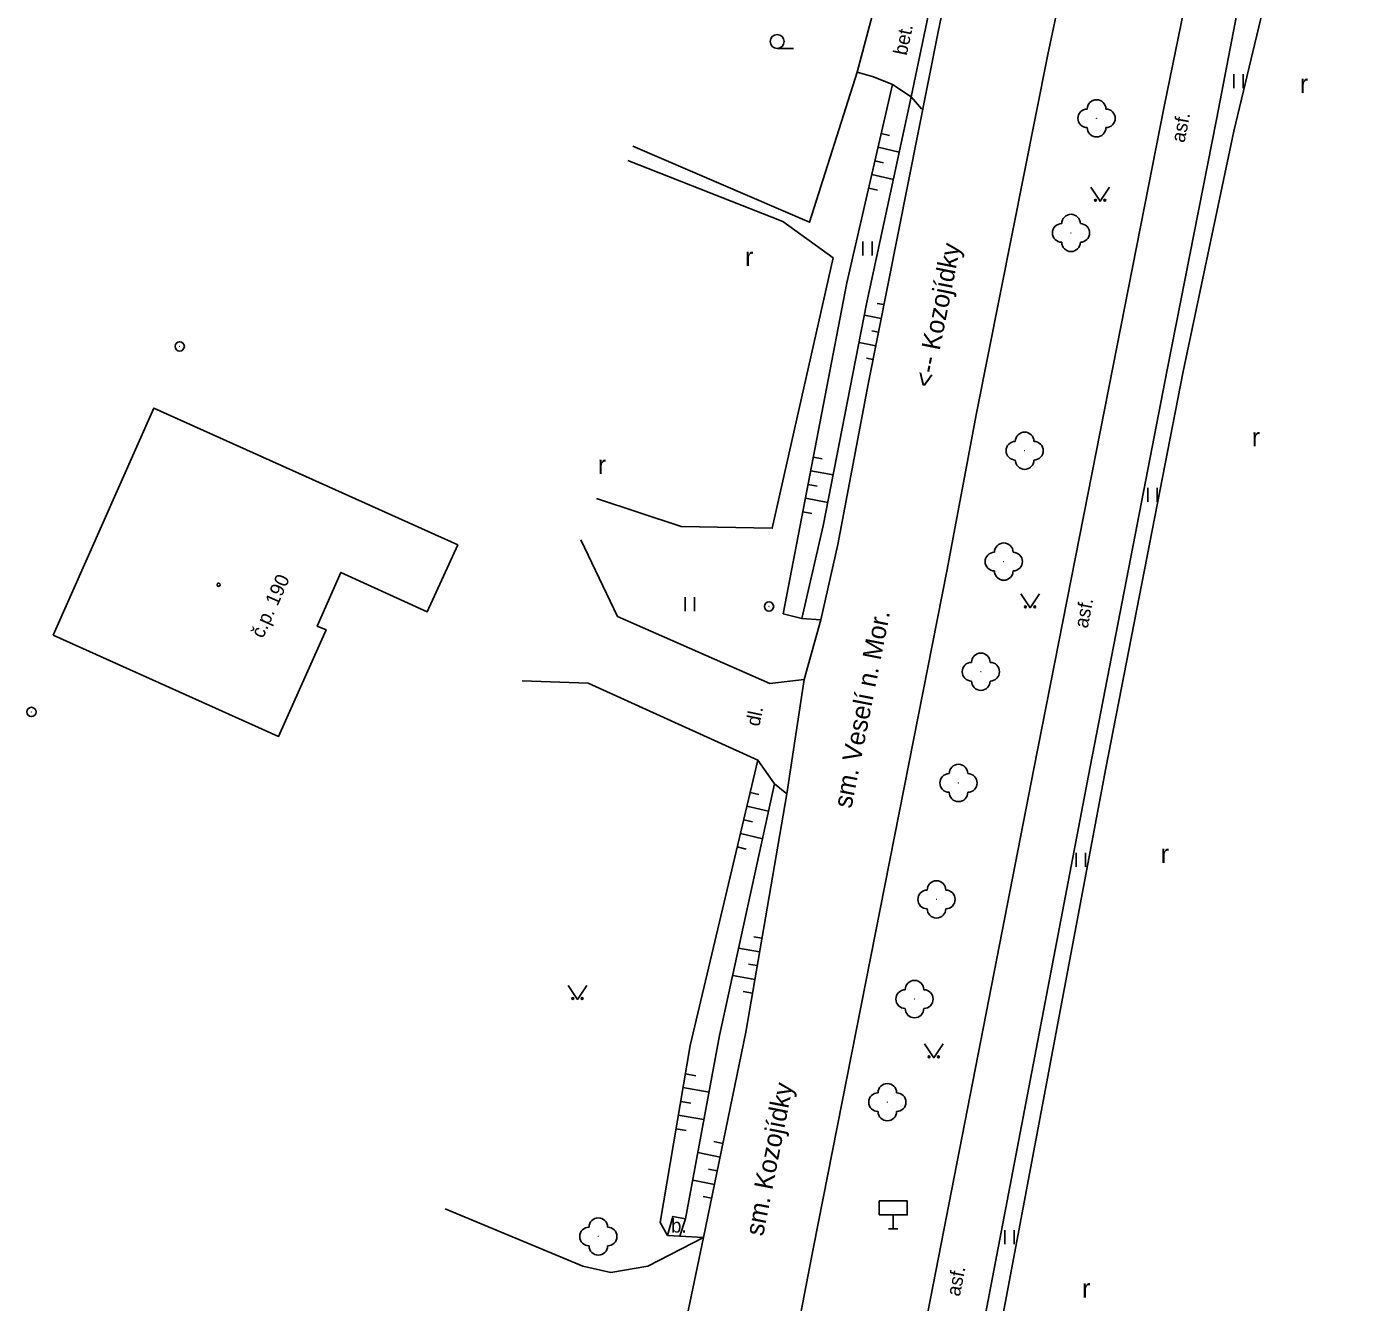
# Model space of a CAD drawing. Extents: x -544674 to -541478, y -1199076 to -1195527.
# Drawn here: x -543843.4 to -543771.7, y -1196778.9 to -1196710.5 of the extents above; entities that cross this region are included whole.
import ezdxf

# ---------------------------------------------------------------- set-up
doc = ezdxf.new("R2010")
doc.units = 0
for name, color, linetype in [('BUDOVY_MĚŘ', 7, 'Continuous'), ('NÁZVY_ULIC_TOK_SMĚR', 7, 'Continuous'), ('POMOC_POPIS', 7, 'Continuous'), ('ROZHRANÍ_PLOCH', 7, 'Continuous'), ('VÝŠKOPIS', 7, 'Continuous'), ('ZELEŇ', 7, 'Continuous'), ('ZN_BP', 7, 'Continuous'), ('ZN_BUDOV', 7, 'Continuous'), ('ZN_DOPLŇKOVÉ', 7, 'Continuous'), ('ZN_KULTUR', 7, 'Continuous'), ('Č_POPIS_ORIENT', 7, 'Continuous')]:
    doc.layers.add(name, color=color, linetype=linetype)

msp = doc.modelspace()

# ---------------------------------------------------------------- linework, layer by layer
at = {"layer": 'BUDOVY_MĚŘ'}
msp.add_lwpolyline([(-543842.03, -1196743.13), (-543829.92, -1196748.56), (-543827.37, -1196742.85), (-543827.85, -1196742.65), (-543826.59, -1196739.76), (-543821.94, -1196741.87), (-543820.31, -1196738.28), (-543836.62, -1196730.94), (-543842.03, -1196743.13)], dxfattribs=at)
at = {"layer": 'ROZHRANÍ_PLOCH'}
for points in [[(-543807.06, -1196806.28), (-543806.75, -1196807.49), (-543805.62, -1196808.57), (-543803.6, -1196809.36), (-543801.75, -1196808.81), (-543800.5, -1196806.91), (-543795.65, -1196782.4), (-543789.39, -1196750.31), (-543785.15, -1196728.76), (-543782.4, -1196714.76), (-543781.01, -1196708.01), (-543777.88, -1196694.39), (-543774.44, -1196682.01), (-543772.54, -1196676.07), (-543769.09, -1196665.96), (-543766.47, -1196658.69), (-543761.92, -1196647.47), (-543762.18, -1196647.29), (-543761.3, -1196645.37), (-543761.06, -1196645.47), (-543756.75, -1196635.37), (-543752.77, -1196625.68), (-543747.9, -1196614.82)], [(-543792.85, -1196784.15), (-543786.36, -1196750.19), (-543782.23, -1196728.89), (-543779.59, -1196715.45), (-543778.13, -1196707.91), (-543774.74, -1196694.16), (-543771.89, -1196683.71), (-543769.45, -1196676.08), (-543766.05, -1196666.53), (-543763.87, -1196660.3), (-543758.86, -1196647.68), (-543758.58, -1196647.85), (-543757.75, -1196645.78), (-543758, -1196645.66), (-543754.11, -1196636.49)], [(-543783.49, -1196669.13), (-543784.44, -1196671.97), (-543785.14, -1196674.25), (-543786.71, -1196679.4), (-543788.2, -1196684.57), (-543789.62, -1196689.76), (-543790.96, -1196694.97), (-543792.22, -1196700.2), (-543793.41, -1196705.44), (-543794.52, -1196710.75)], [(-543777.74, -1196671.33), (-543779.43, -1196676.6), (-543781.04, -1196681.89), (-543782.57, -1196687.2), (-543784.03, -1196692.54), (-543785.41, -1196697.89), (-543786.71, -1196703.27), (-543787.93, -1196708.66), (-543788.64, -1196711.96)], [(-543794.52, -1196710.75), (-543798.28, -1196729.66), (-543799.91, -1196738.27)], [(-543788.64, -1196711.96), (-543792.46, -1196731.22), (-543794.06, -1196739.69)], [(-543795.4, -1196714.9), (-543795.97, -1196714.24), (-543796.98, -1196713.57), (-543797.99, -1196713.17), (-543798.86, -1196712.91)], [(-543800.82, -1196742.31), (-543801.72, -1196745.51), (-543803.56, -1196745.72), (-543811.73, -1196742.12), (-543813.7, -1196738.01)], [(-543800.82, -1196742.31), (-543799.91, -1196738.27)], [(-543807.06, -1196806.28), (-543801.22, -1196775.98), (-543794.06, -1196739.69)], [(-543802.65, -1196751.65), (-543803.3, -1196751.1), (-543804.2, -1196749.83), (-543813.31, -1196745.71), (-543816.84, -1196745.57)], [(-543801.72, -1196745.51), (-543802.65, -1196751.65)], [(-543802.65, -1196751.65), (-543804.85, -1196764.44), (-543807.11, -1196775.45)], [(-543807.11, -1196775.45), (-543810.1, -1196777), (-543812.09, -1196777.33), (-543813.59, -1196777), (-543820.99, -1196773.91)], [(-543809.05, -1196775.34), (-543808.39, -1196775.39), (-543808.08, -1196774.45), (-543808.76, -1196774.32), (-543809.05, -1196775.34)], [(-543807.11, -1196775.45), (-543809.56, -1196787.17)]]:
    msp.add_lwpolyline(points, dxfattribs=at)
at = {"layer": 'VÝŠKOPIS'}
for points in [[(-543796.98, -1196713.57), (-543799.42, -1196724.22), (-543802.84, -1196741.98), (-543801.84, -1196742.24), (-543800.82, -1196742.31)], [(-543795.97, -1196714.24), (-543798.36, -1196725.35), (-543800.69, -1196737.26), (-543801.84, -1196742.24)], [(-543797.58, -1196716.21), (-543797.13, -1196716.31)], [(-543797.75, -1196716.94), (-543796.61, -1196717.2)], [(-543797.92, -1196717.67), (-543797.46, -1196717.77)], [(-543798.09, -1196718.4), (-543796.92, -1196718.67)], [(-543798.25, -1196719.13), (-543797.78, -1196719.24)], [(-543797.43, -1196725.39), (-543797.79, -1196725.32)], [(-543797.58, -1196726.13), (-543798.48, -1196725.95)], [(-543797.72, -1196726.86), (-543798.08, -1196726.79)], [(-543797.87, -1196727.6), (-543798.76, -1196727.42)], [(-543798.02, -1196728.33), (-543798.37, -1196728.26)], [(-543801.22, -1196733.57), (-543800.74, -1196733.66)], [(-543801.36, -1196734.3), (-543800.16, -1196734.53)], [(-543801.5, -1196735.04), (-543801.02, -1196735.13)], [(-543801.65, -1196735.78), (-543800.44, -1196736.01)], [(-543801.79, -1196736.51), (-543801.31, -1196736.6)], [(-543804.2, -1196749.83), (-543807.83, -1196765.15), (-543809.45, -1196774.65), (-543809.05, -1196775.34)], [(-543803.3, -1196751.1), (-543806.25, -1196764.62), (-543808.08, -1196774.45)], [(-543804.61, -1196751.58), (-543804.15, -1196751.68)], [(-543804.79, -1196752.31), (-543803.62, -1196752.58)], [(-543804.96, -1196753.04), (-543804.49, -1196753.15)], [(-543805.13, -1196753.77), (-543803.94, -1196754.05)], [(-543805.31, -1196754.49), (-543804.82, -1196754.61)], [(-543804.11, -1196760.12), (-543805.23, -1196759.93)], [(-543803.98, -1196759.39), (-543804.42, -1196759.31)], [(-543804.36, -1196761.6), (-543805.55, -1196761.4)], [(-543804.23, -1196760.86), (-543804.7, -1196760.78)], [(-543804.49, -1196762.34), (-543804.98, -1196762.26)], [(-543808.09, -1196766.67), (-543807.52, -1196766.77)], [(-543808.22, -1196767.41), (-543806.81, -1196767.65)], [(-543808.34, -1196768.15), (-543807.79, -1196768.24)], [(-543808.47, -1196768.89), (-543807.09, -1196769.12)], [(-543808.59, -1196769.63), (-543808.05, -1196769.72)], [(-543806.07, -1196770.41), (-543806.56, -1196770.31)], [(-543806.23, -1196771.14), (-543807.42, -1196770.9)], [(-543806.38, -1196771.88), (-543806.85, -1196771.78)], [(-543806.53, -1196772.61), (-543807.69, -1196772.37)], [(-543806.68, -1196773.35), (-543807.14, -1196773.25)], [(-543808.39, -1196775.39), (-543807.11, -1196775.45)]]:
    msp.add_lwpolyline(points, dxfattribs=at)
at = {"layer": 'ZELEŇ'}
for points in [[(-543781.96, -1196809.38), (-543794.69, -1196802.87), (-543792.17, -1196785.64), (-543785.53, -1196750.27), (-543781.37, -1196728.98), (-543778.66, -1196716.08), (-543776.59, -1196707.48), (-543772.72, -1196694.21), (-543770.96, -1196689.69), (-543766.47, -1196689.13), (-543759.47, -1196692.13), (-543741.82, -1196700.81)], [(-543811.18, -1196717.66), (-543802.86, -1196720.92), (-543800.16, -1196722.88), (-543803.43, -1196737.39), (-543808.32, -1196737.3), (-543812.86, -1196735.79)]]:
    msp.add_lwpolyline(points, dxfattribs=at)
for centre in [(-543786.02, -1196715.39), (-543787.39, -1196721.54), (-543789.88, -1196733.23), (-543791, -1196739.18), (-543792.23, -1196745.09), (-543793.43, -1196751.06), (-543794.61, -1196757.31), (-543795.79, -1196762.66), (-543797.25, -1196768.19), (-543812.76, -1196775.4)]:
    msp.add_circle(centre, 0.0005, dxfattribs=at)
for centre, start, end in [((-543786.02, -1196714.89), 0, 179.99999), ((-543786.52, -1196715.39), 89.99999, 269.99999), ((-543785.52, -1196715.39), 270, 89.99999), ((-543786.02, -1196715.89), 179.99999, 359.99999), ((-543787.39, -1196721.04), 0, 179.99999), ((-543787.89, -1196721.54), 89.99999, 269.99999), ((-543786.89, -1196721.54), 270, 89.99999), ((-543787.39, -1196722.04), 179.99999, 359.99999), ((-543790.38, -1196733.23), 89.99999, 269.99999), ((-543789.88, -1196732.73), 0, 179.99999), ((-543789.38, -1196733.23), 270, 89.99999), ((-543789.88, -1196733.73), 179.99999, 359.99999), ((-543791, -1196738.68), 0, 179.99999), ((-543791.5, -1196739.18), 89.99999, 269.99999), ((-543790.5, -1196739.18), 270, 89.99999), ((-543791, -1196739.68), 179.99999, 359.99999), ((-543792.23, -1196744.59), 0, 179.99999), ((-543792.73, -1196745.09), 89.99999, 269.99999), ((-543791.73, -1196745.09), 270, 89.99999), ((-543792.23, -1196745.59), 179.99999, 359.99999), ((-543793.93, -1196751.06), 89.99999, 269.99999), ((-543793.43, -1196750.56), 0, 179.99999), ((-543792.93, -1196751.06), 270, 89.99999), ((-543793.43, -1196751.56), 179.99999, 359.99999), ((-543794.61, -1196756.81), 0, 179.99999), ((-543795.11, -1196757.31), 89.99999, 269.99999), ((-543794.11, -1196757.31), 270, 89.99999), ((-543794.61, -1196757.81), 179.99999, 359.99999), ((-543796.29, -1196762.66), 89.99999, 269.99999), ((-543795.79, -1196762.16), 0, 179.99999), ((-543795.29, -1196762.66), 270, 89.99999), ((-543795.79, -1196763.16), 179.99999, 359.99999), ((-543797.25, -1196767.69), 0, 179.99999), ((-543797.75, -1196768.19), 89.99999, 269.99999), ((-543796.75, -1196768.19), 270, 89.99999), ((-543797.25, -1196768.69), 179.99999, 359.99999), ((-543813.26, -1196775.4), 89.99999, 269.99999), ((-543812.76, -1196774.9), 0, 179.99999), ((-543812.26, -1196775.4), 270, 89.99999), ((-543812.76, -1196775.9), 179.99999, 359.99999)]:
    msp.add_arc(centre, 0.5, start, end, dxfattribs=at)
at = {"layer": 'ZN_BP'}
for centre, radius in [((-543835.23, -1196727.63), 0.25), ((-543835.23, -1196727.63), 0.0005), ((-543803.6, -1196741.59), 0.25), ((-543803.6, -1196741.59), 0.0005), ((-543843.19, -1196747.25), 0.25), ((-543843.19, -1196747.25), 0.0005)]:
    msp.add_circle(centre, radius, dxfattribs=at)
at = {"layer": 'ZN_BUDOV'}
msp.add_circle((-543833.14, -1196740.42), 0.0875, dxfattribs=at)
at = {"layer": 'ZN_DOPLŇKOVÉ'}
for p, q in [((-543796.93, -1196774.24), (-543796.93, -1196774.99)), ((-543797.18, -1196774.99), (-543796.68, -1196774.99))]:
    msp.add_line(p, q, dxfattribs=at)
for points in [[(-543794.5, -1196707.22), (-543795.97, -1196714.24)], [(-543797.62, -1196708.19), (-543798.86, -1196712.91)], [(-543810.91, -1196716.89), (-543801.43, -1196720.97), (-543798.86, -1196712.91)]]:
    msp.add_lwpolyline(points, dxfattribs=at)
msp.add_lwpolyline([(-543797.68, -1196774.24), (-543796.18, -1196774.24), (-543796.18, -1196773.49), (-543797.68, -1196773.49)], close=True, dxfattribs=at)
at = {"layer": 'ZN_KULTUR'}
for p, q in [((-543803.16, -1196711.645), (-543802.285, -1196711.645)), ((-543778.65, -1196713.765), (-543778.65, -1196713.015)), ((-543778.15, -1196713.765), (-543778.15, -1196713.015)), ((-543798.56, -1196722.745), (-543798.56, -1196721.995)), ((-543798.06, -1196722.745), (-543798.06, -1196721.995)), ((-543783.26, -1196735.965), (-543783.26, -1196735.215)), ((-543782.76, -1196735.965), (-543782.76, -1196735.215)), ((-543808.1, -1196741.845), (-543808.1, -1196741.095)), ((-543807.6, -1196741.845), (-543807.6, -1196741.095)), ((-543787.11, -1196755.555), (-543787.11, -1196754.805)), ((-543786.61, -1196755.555), (-543786.61, -1196754.805)), ((-543790.94, -1196775.815), (-543790.94, -1196775.065)), ((-543790.44, -1196775.815), (-543790.44, -1196775.065))]:
    msp.add_line(p, q, dxfattribs=at)
for points in [[(-543786.33, -1196719.09), (-543785.83, -1196719.84), (-543785.33, -1196719.09)], [(-543790.09, -1196740.91), (-543789.59, -1196741.66), (-543789.09, -1196740.91)], [(-543814.38, -1196761.93), (-543813.88, -1196762.68), (-543813.38, -1196761.93)], [(-543795.26, -1196765.06), (-543794.76, -1196765.81), (-543794.26, -1196765.06)]]:
    msp.add_lwpolyline(points, dxfattribs=at)
for centre, radius in [((-543803.16, -1196711.27), 0.375), ((-543786.08, -1196719.79), 0.05), ((-543785.58, -1196719.79), 0.05), ((-543789.84, -1196741.61), 0.05), ((-543789.34, -1196741.61), 0.05), ((-543814.13, -1196762.63), 0.05), ((-543813.63, -1196762.63), 0.05), ((-543795.01, -1196765.76), 0.05), ((-543794.51, -1196765.76), 0.05)]:
    msp.add_circle(centre, radius, dxfattribs=at)

# ---------------------------------------------------------------- texts
at = {"layer": 'NÁZVY_ULIC_TOK_SMĚR'}
for s, rotation, p in [('<-- Kozojídky', 78.77998, (-543794.84, -1196729.89)), ('sm. Veselí n. Mor.', 78.84002, (-543799.18, -1196752.46)), ('sm. Kozojídky', 78.84002, (-543803.92, -1196775.42))]:
    msp.add_text(s, height=1, rotation=rotation, dxfattribs=at).set_placement(p)
at = {"layer": 'POMOC_POPIS'}
for s, rotation, p in [('bet.', 78.17306, (-543796.21, -1196712.05)), ('asf.', 78.88696, (-543781.3, -1196716.73)), ('asf.', 79.0267, (-543786.5, -1196742.79)), ('dl.', 78.31675, (-543804.12, -1196748.06)), ('asf.', 78.96158, (-543793.36, -1196778.65))]:
    msp.add_text(s, height=0.75, rotation=rotation, dxfattribs=at).set_placement(p)
msp.add_text('b.', height=0.75, dxfattribs=at).set_placement((-543808.86, -1196775.19))
at = {"layer": 'ZN_KULTUR'}
for p in [(-543775.108, -1196714.032), (-543804.888, -1196723.322), (-543777.688, -1196733.002), (-543812.788, -1196734.482), (-543782.578, -1196755.362), (-543786.798, -1196778.682)]:
    msp.add_text('r', height=1, dxfattribs=at).set_placement(p)
at = {"layer": 'Č_POPIS_ORIENT'}
msp.add_text('č.p. 190', height=0.75, rotation=65.93518, dxfattribs=at).set_placement((-543830.76, -1196743.34))

doc.saveas('drawing.dxf')
